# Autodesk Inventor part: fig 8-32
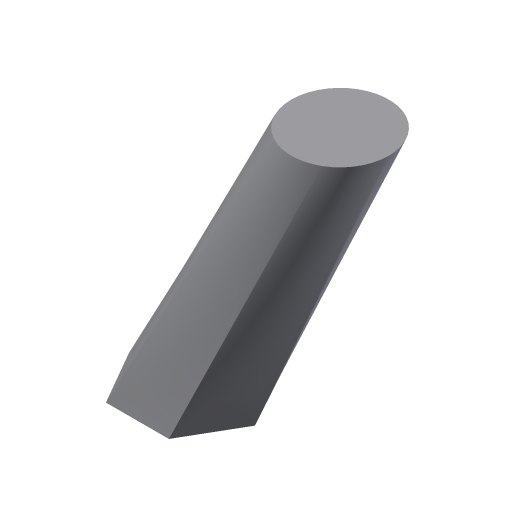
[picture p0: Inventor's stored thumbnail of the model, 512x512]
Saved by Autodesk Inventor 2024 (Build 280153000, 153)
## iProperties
Shininess: 77.0
Angle Display Precision: 2
Document Length Units: 11269
Document Angle Units: 11279
Document Time Units: 11290
Document Mass Units: 11283
Document Length Units Precision: 3
Document Angle Units Precision: 2
Created: 2001-12
Part Number: fig 8-32
Document SubType Name: Modeling
Designer: CADSoft
Density: 1 g/cm^3
Material: Generic
Appearance: Default
Density: 0.0
Volumn: 0.0
Area: 0.0
PropertySet Name: Model Information
Control State: 0
Master: False
Checked Out: False
Author: CADSoft
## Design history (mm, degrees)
workplane "Work Plane3"
workplane "Work Plane4"
sketch "Sketch12"
  geometry: L1 (0, 10.598)-(9.178, -5.299); L2 (9.178, -5.299)-(-9.178, -5.299); L3 (-9.178, -5.299)-(0, 10.598); 1 further point
  constraints: 6 end point, 5 other
workplane "Work Plane5"
workplane "Work Plane6"
workplane "Work Plane7"
sketch "Sketch16"
  geometry: A1 r 72.799 centre (23.007, 110.594) between (0, 41.527) and (70, 54.995); 1 further point
  constraints: 2 point on circle, 1 centre point
loft "Loft5" dims "d57" = 0, "d58" = 90 deg, "d59" = 0, "d60" = 90 deg
body "Solid2"
sketch "Sketch1"
  geometry: L1 (19.387, 0)-(9.693, -16.79); L2 (9.693, -16.79)-(-9.693, -16.79); L3 (-9.693, -16.79)-(-19.387, 0); L4 (-19.387, 0)-(-9.693, 16.79); L5 (-9.693, 16.79)-(9.693, 16.79); L6 (9.693, 16.79)-(19.387, 0); 1 further point
  constraints: 12 end point, 11 other
sketch "Sketch2"
  geometry: C1 r 15 at (23.06, 22.535)
  constraints: 1 centre point
